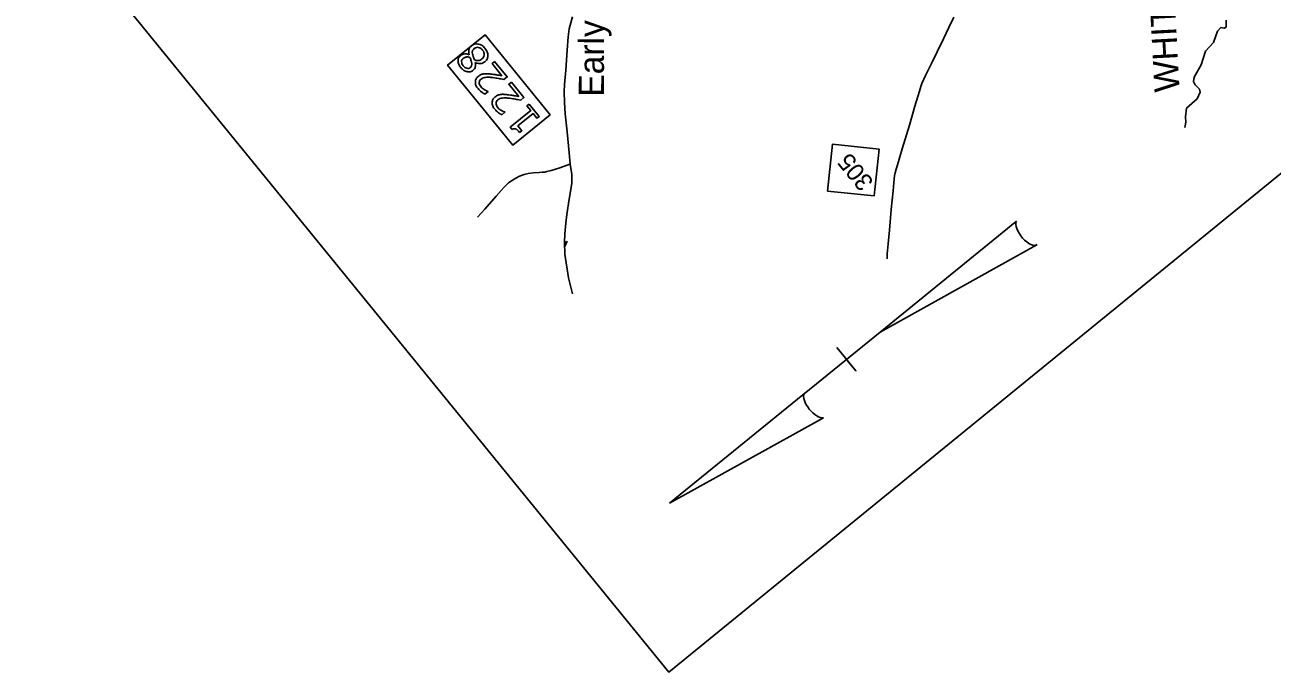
# Model space of a CAD drawing. Extents: x 2596159 to 2598075, y 851667 to 853493.
# Drawn here: x 2596982.3 to 2597281.5, y 851666.6 to 851821.9 of the extents above; entities that cross this region are included whole.
import ezdxf

# ---------------------------------------------------------------- set-up
doc = ezdxf.new("R2010")
doc.units = 0
doc.layers.add('Old_Level_1', color=7, linetype='Continuous')
doc.layers.add('Old_Level_18', color=7, linetype='Continuous')

msp = doc.modelspace()

# ---------------------------------------------------------------- linework, layer by layer
at = {"layer": 'Old_Level_1'}
for p, q in [((2597113.71, 851823.82), (2597113.09, 851821.84)), ((2597205.2, 851823.73), (2597203.98, 851821.31)), ((2597112.88, 851820.95), (2597112.67, 851819.02)), ((2597113.09, 851821.84), (2597112.88, 851820.95)), ((2597203.98, 851821.31), (2597202.65, 851818.55)), ((2597268.45, 851820.4), (2597267.49, 851817.71)), ((2597269.18, 851821.28), (2597268.45, 851820.4)), ((2597270, 851821.13), (2597269.18, 851821.28)), ((2597270.49, 851821.36), (2597270, 851821.13)), ((2597270.51, 851823.03), (2597270.49, 851821.36)), ((2597108.3, 851800.35), (2597092.69, 851819.55)), ((2597112.67, 851819.02), (2597112.41, 851815.83)), ((2597202.65, 851818.55), (2597201.16, 851815.45)), ((2597267.49, 851817.71), (2597265.52, 851815.59)), ((2597112.41, 851815.83), (2597112.07, 851811.05)), ((2597201.16, 851815.45), (2597199.81, 851812.65)), ((2597265.52, 851815.59), (2597264.5, 851812.35)), ((2597199.81, 851812.65), (2597198.4, 851809.76)), ((2597264.5, 851812.35), (2597262.83, 851809.32)), ((2597112.07, 851811.05), (2597111.76, 851807.63)), ((2597198.4, 851809.76), (2597197.5, 851807.85)), ((2597262.83, 851809.32), (2597262.67, 851808.34)), ((2597262.67, 851808.34), (2597263.06, 851807.48)), ((2597111.76, 851807.63), (2597111.65, 851805.87)), ((2597111.65, 851805.87), (2597111.79, 851803.27)), ((2597196.91, 851806.01), (2597195.77, 851802.41)), ((2597197.22, 851807.09), (2597196.91, 851806.01)), ((2597197.5, 851807.85), (2597197.22, 851807.09)), ((2597263.06, 851807.48), (2597263.52, 851807.01)), ((2597264.28, 851805.78), (2597263.51, 851804.14)), ((2597263.52, 851807.01), (2597264.11, 851806.51)), ((2597264.11, 851806.51), (2597264.28, 851805.78)), ((2597111.79, 851803.27), (2597111.95, 851800.56)), ((2597195.77, 851802.41), (2597194.56, 851797.86)), ((2597263.51, 851804.14), (2597261.01, 851801.94)), ((2597111.95, 851800.56), (2597112.37, 851796.21)), ((2597261.01, 851801.94), (2597260.71, 851799.84)), ((2597260.71, 851799.84), (2597260.78, 851798.53)), ((2597194.56, 851797.86), (2597192.8, 851792.17)), ((2597260.67, 851797.66), (2597260.58, 851797.26)), ((2597260.78, 851798.53), (2597260.67, 851797.66)), ((2597112.37, 851796.21), (2597112.85, 851791.18)), ((2597112.85, 851791.18), (2597113.14, 851788.45)), ((2597192.8, 851792.17), (2597191.48, 851787.8)), ((2597110.4, 851787.56), (2597108.55, 851787)), ((2597112.67, 851788.29), (2597110.4, 851787.56)), ((2597113.14, 851788.45), (2597112.67, 851788.29)), ((2597113.14, 851788.45), (2597113.53, 851786.04)), ((2597191.34, 851787.31), (2597191.09, 851786.38)), ((2597191.48, 851787.8), (2597191.34, 851787.31)), ((2597099.07, 851784.52), (2597098.33, 851784)), ((2597100.06, 851785.16), (2597099.07, 851784.52)), ((2597100.97, 851785.58), (2597100.06, 851785.16)), ((2597102.09, 851785.99), (2597100.97, 851785.58)), ((2597103.01, 851786.22), (2597102.09, 851785.99)), ((2597104.23, 851786.39), (2597103.01, 851786.22)), ((2597105.68, 851786.47), (2597104.23, 851786.39)), ((2597106.44, 851786.53), (2597105.68, 851786.47)), ((2597107.01, 851786.6), (2597106.44, 851786.53)), ((2597107.56, 851786.71), (2597107.01, 851786.6)), ((2597108.55, 851787), (2597107.56, 851786.71)), ((2597113.55, 851784.87), (2597113.5, 851783.83)), ((2597113.53, 851786.04), (2597113.55, 851784.87)), ((2597190.84, 851785), (2597190.59, 851782.07)), ((2597190.95, 851785.66), (2597190.84, 851785)), ((2597191.09, 851786.38), (2597190.95, 851785.66)), ((2597096.56, 851782.13), (2597095.38, 851780.83)), ((2597097.31, 851782.98), (2597096.56, 851782.13)), ((2597097.77, 851783.47), (2597097.31, 851782.98)), ((2597098.33, 851784), (2597097.77, 851783.47)), ((2597113.5, 851783.83), (2597112.88, 851780.09)), ((2597190.59, 851782.07), (2597190.15, 851777.57)), ((2597095.38, 851780.83), (2597092.62, 851777.7)), ((2597112.88, 851780.09), (2597112.29, 851776.39)), ((2597092.62, 851777.7), (2597090.86, 851775.74)), ((2597112.29, 851776.39), (2597112.11, 851774.32)), ((2597190.15, 851777.57), (2597189.69, 851772.63)), ((2597112.11, 851774.32), (2597111.86, 851771.8)), ((2597220.17, 851774.83), (2597187.46, 851748.19)), ((2597189.69, 851772.63), (2597189.39, 851769.34)), ((2597111.86, 851771.8), (2597111.78, 851769.73)), ((2597111.78, 851769.73), (2597111.82, 851766.9)), ((2597111.8, 851768.53), (2597112.44, 851769.98)), ((2597112.01, 851769.97), (2597111.8, 851769.48)), ((2597189.39, 851769.34), (2597189.2, 851766.99)), ((2597111.82, 851766.9), (2597112.73, 851761.19)), ((2597187.46, 851748.19), (2597225.06, 851769.1)), ((2597189.2, 851766.99), (2597189.13, 851765.78)), ((2597112.73, 851761.19), (2597113.65, 851757.35)), ((2597187.46, 851748.19), (2597169.24, 851733.38)), ((2597181.63, 851738.88), (2597177.1, 851744.45)), ((2597179.65, 851741.32), (2597181.66, 851738.85)), ((2597181.66, 851738.85), (2597181.68, 851738.81)), ((2597136.96, 851707.14), (2597170.21, 851734.17)), ((2597170.21, 851734.17), (2597169.27, 851733.4)), ((2597173.87, 851727.61), (2597136.99, 851707.11)), ((2597136.96, 851707.14), (2597136.99, 851707.11)), ((2597136.96, 851707.14), (2597136.99, 851707.11))]:
    msp.add_line(p, q, dxfattribs=at)
for points in [[(2597108.3, 851800.35), (2597092.69, 851819.55), (2597083.73, 851812.27), (2597099.33, 851793.06), (2597108.3, 851800.35)], [(2597088.89, 851814.71), (2597088.91, 851814.72)], [(2597090.36, 851812.88), (2597090.34, 851812.86)], [(2597096.76, 851809.68), (2597094.37, 851812.62), (2597095, 851813.14)], [(2597095, 851813.14), (2597098.02, 851809.43), (2597097.24, 851808.8)], [(2597093.4, 851805.97), (2597093.43, 851805.93), (2597092.66, 851805.3)], [(2597100.79, 851804.72), (2597098.4, 851807.66), (2597099.03, 851808.18)], [(2597099.03, 851808.18), (2597102.04, 851804.47), (2597101.27, 851803.85)], [(2597099.2, 851796.77), (2597098.74, 851797.34), (2597103.66, 851801.34), (2597102.76, 851802.46), (2597103.32, 851802.91)], [(2597103.32, 851802.91), (2597105.72, 851799.95), (2597105.16, 851799.5), (2597104.24, 851800.64), (2597100.57, 851797.66), (2597101.5, 851796.52), (2597101, 851796.11)], [(2597097.43, 851801.01), (2597097.46, 851800.97), (2597096.69, 851800.35)]]:
    msp.add_lwpolyline(points, dxfattribs=at)
msp.add_lwpolyline([(2597186.08, 851780.86), (2597174.86, 851782.02), (2597176.02, 851793.25), (2597187.24, 851792.09)], close=True, dxfattribs=at)
for centre, start_param, end_param in [((2597222.78, 851772.14), 0.201328, 3.141593), ((2597171.87, 851730.77), 0.216388, 2.908219)]:
    msp.add_ellipse(centre, major_axis=(-2.37, 2.96), ratio=0.461098, start_param=start_param, end_param=end_param, dxfattribs=at)
for points in [[(2597089.42, 851816.89), (2597090.13, 851817.47), (2597091.05, 851817.3), (2597091.97, 851817.13), (2597092.65, 851816.29), (2597093.37, 851815.4), (2597093.34, 851814.5), (2597093.31, 851813.6), (2597092.59, 851813.02), (2597092.14, 851812.65), (2597091.56, 851812.61), (2597090.97, 851812.58), (2597090.36, 851812.88)], [(2597090.34, 851812.86), (2597090.46, 851812.23), (2597090.36, 851811.79), (2597090.25, 851811.36), (2597089.83, 851811.02), (2597089.21, 851810.51), (2597088.39, 851810.69), (2597087.57, 851810.86), (2597086.93, 851811.64), (2597086.26, 851812.46), (2597086.26, 851813.27), (2597086.26, 851814.08), (2597086.86, 851814.57), (2597087.23, 851814.87), (2597087.78, 851814.93), (2597088.33, 851814.99), (2597088.89, 851814.71)], [(2597087.46, 851813.85), (2597087.06, 851813.53), (2597087.08, 851813.04), (2597087.09, 851812.55), (2597087.47, 851812.08), (2597087.85, 851811.61), (2597088.31, 851811.5), (2597088.77, 851811.38), (2597089.15, 851811.68), (2597089.41, 851811.9), (2597089.48, 851812.2), (2597089.56, 851812.51), (2597089.46, 851812.93), (2597089.42, 851813.12), (2597089.32, 851813.47), (2597089.21, 851813.81), (2597089.09, 851814.11), (2597088.55, 851814.27), (2597088.17, 851814.2), (2597087.8, 851814.13), (2597087.46, 851813.85)], [(2597088.91, 851814.72), (2597088.72, 851815.42), (2597088.82, 851815.95), (2597088.92, 851816.49), (2597089.42, 851816.89)], [(2597090.1, 851816.2), (2597089.76, 851815.92), (2597089.68, 851815.61), (2597089.6, 851815.29), (2597089.75, 851814.69), (2597089.81, 851814.45), (2597089.9, 851814.19), (2597090, 851813.93), (2597090.15, 851813.48), (2597090.6, 851813.3), (2597091.07, 851813.35), (2597091.54, 851813.4), (2597091.93, 851813.72), (2597092.43, 851814.12), (2597092.47, 851814.72), (2597092.52, 851815.33), (2597092.09, 851815.85), (2597091.66, 851816.39), (2597091.12, 851816.49), (2597090.58, 851816.59), (2597090.1, 851816.2)], [(2597092.66, 851805.3), (2597092.32, 851805.46), (2597091.86, 851805.81), (2597091.4, 851806.16), (2597091.07, 851806.57), (2597090.39, 851807.41), (2597090.4, 851808.22), (2597090.42, 851809.02), (2597091.11, 851809.59), (2597091.43, 851809.84), (2597091.76, 851809.98), (2597092.09, 851810.12), (2597092.46, 851810.16), (2597092.81, 851810.21), (2597093.18, 851810.19), (2597093.56, 851810.18), (2597094.05, 851810.12), (2597094.76, 851810.04), (2597095.46, 851809.91), (2597096.16, 851809.79), (2597096.76, 851809.68)], [(2597097.24, 851808.8), (2597096.6, 851808.92), (2597095.95, 851809.04), (2597095.31, 851809.16), (2597094.71, 851809.23), (2597093.45, 851809.38), (2597092.84, 851809.32), (2597092.22, 851809.25), (2597091.76, 851808.87), (2597091.33, 851808.53), (2597091.32, 851808.05), (2597091.31, 851807.57), (2597091.72, 851807.07), (2597091.99, 851806.73), (2597092.42, 851806.44), (2597092.86, 851806.14), (2597093.4, 851805.97)], [(2597096.69, 851800.35), (2597096.35, 851800.5), (2597095.89, 851800.85), (2597095.43, 851801.2), (2597095.1, 851801.61), (2597094.41, 851802.45), (2597094.43, 851803.26), (2597094.45, 851804.07), (2597095.14, 851804.63), (2597095.45, 851804.89), (2597095.79, 851805.03), (2597096.12, 851805.17), (2597096.49, 851805.21), (2597096.83, 851805.25), (2597097.21, 851805.24), (2597097.59, 851805.22), (2597098.08, 851805.16), (2597098.78, 851805.08), (2597099.49, 851804.96), (2597100.19, 851804.83), (2597100.79, 851804.72)], [(2597101.27, 851803.85), (2597100.63, 851803.96), (2597099.98, 851804.08), (2597099.33, 851804.2), (2597098.74, 851804.27), (2597097.48, 851804.42), (2597096.86, 851804.36), (2597096.25, 851804.29), (2597095.78, 851803.92), (2597095.36, 851803.57), (2597095.35, 851803.09), (2597095.34, 851802.61), (2597095.75, 851802.11), (2597096.02, 851801.77), (2597096.45, 851801.48), (2597096.89, 851801.18), (2597097.43, 851801.01)], [(2597101, 851796.11), (2597100.81, 851796.34), (2597100.56, 851796.58), (2597100.3, 851796.81), (2597100.12, 851796.89), (2597099.89, 851796.98), (2597099.67, 851796.96), (2597099.45, 851796.95), (2597099.2, 851796.77)]]:
    msp.add_open_spline(points, degree=3, dxfattribs=at)
at = {"layer": 'Old_Level_18'}
msp.add_lwpolyline([(2596922.78, 851929.12), (2596189.05, 852829.31), (2597002.93, 853492.71), (2597950.65, 852330), (2597136.77, 851666.6), (2596922.78, 851929.12)], dxfattribs=at)

# ---------------------------------------------------------------- texts
at = {"layer": 'Old_Level_1'}
for s, height, rotation, p in [('WHITE OAK SWAMP', 6.0253, 93.0451, (2597259.34, 851805.93)), ('Early Station Rd', 6.0253, 89.9225, (2597121.22, 851804.67)), ('305', 4.193, 129.1029, (2597186.1, 851784.25))]:
    msp.add_text(s, height=height, rotation=rotation, dxfattribs=at).set_placement(p)

doc.saveas('drawing.dxf')
